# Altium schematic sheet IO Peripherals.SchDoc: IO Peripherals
size A4; DocumentNumber: 6; Revision: D.1(PCB.SCH); SheetNumber: 5; SheetTotal: 5
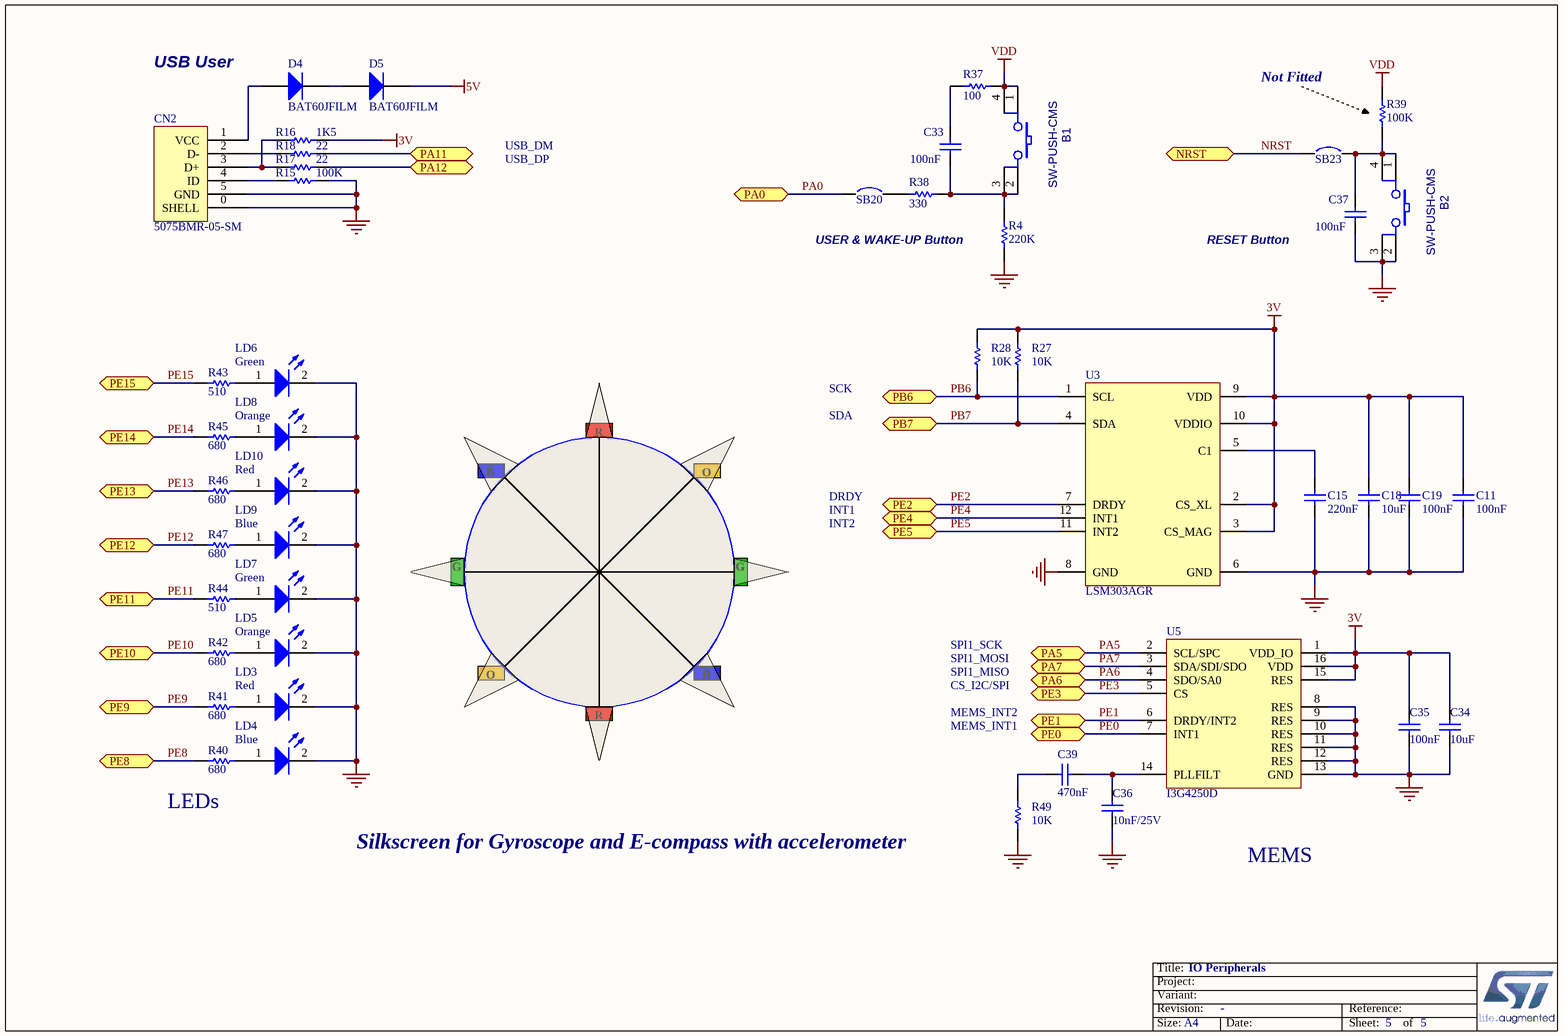
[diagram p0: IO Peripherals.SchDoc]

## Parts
B1  SW-PUSH-CMS  [BP1CMS]
B2  SW-PUSH-CMS  [BP1CMS]
C11  100nF  [0603C]
C15  220nF  [0603C]
C18  10uF  [0603C]
C19  100nF  [0603C]
C33  100nF  [0603C]
C34  10uF  [0603C]
C35  100nF  [0603C]
C36  10nF/25V  [0603C]
C37  100nF  [0603C]
C39  value 470nF  [C0603]  (hidden comment: Capacitor)
CN2  5075BMR-05-SM  [USB-MINI-B-SMD]
D4  BAT60JFILM  [SOD323/A]
D5  BAT60JFILM  [SOD323/A]
LD3  Red  [0603D]
LD4  Blue  [0603D]
LD5  Orange  [0603D]
LD6  Green  [0603D]
LD7  Green  [0603D]
LD8  Orange  [0603D]
LD9  Blue  [0603D]
LD10  Red  [0603D]
R4  220K  [0603R]
R15  100K  [0402R]
R16  1K5  [0402R]
R17  22  [0402R]
R18  22  [0402R]
R27  10K  [0402R]
R28  10K  [0402R]
R37  100  [0402R]
R38  330  [0402R]
R39  100K  [0402R]
R40  680  [0603R]
R41  680  [0603R]
R42  680  [0603R]
R43  510  [0603R]
R44  510  [0603R]
R45  680  [0603R]
R46  680  [0603R]
R47  680  [0603R]
R49  10K  [0402R]
SB20  Circuit Breaker  [JP2_SMD]  (value not drawn)
SB23  Circuit Breaker  [JP2_SMD]  (value not drawn)
U3  LSM303AGR  [ICC_LGA12_2X2_P050]
U5  I3G4250D  [ICC_LGA16_4X4_P065_H1P1]

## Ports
NRST, PA0, PA5, PA6, PA7, PA11, PA12, PB6, PB7, PE0, PE1, PE2, PE3, PE4, PE5, PE8, PE9, PE10, PE11, PE12, PE13, PE14, PE15

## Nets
3V: C11.1 C18.2 C19.2 C34.2 C35.2 R16.2 R27.1 R28.1 U3.2(CS_XL) U3.3(CS_MAG) U3.9(VDD) U3.10(VDDIO) U5.1(VDD_IO) U5.15(RES) U5.16(VDD)
5V: D5.2(K)
GND: B2.2 B2.3 C11.2 C15.1 C18.1 C19.1 C34.1 C35.1 C36.1 C37.1 CN2.0(SHELL) CN2.5(GND) LD3.2(K) LD4.2(K) LD5.2(K) LD6.2(K) LD7.2(K) LD8.2(K) LD9.2(K) LD10.2(K) R4.1 R15.2 R49.2 U3.6(GND) U3.8(GND) U5.8(RES) U5.9(RES) U5.10(RES) U5.11(RES) U5.12(RES) U5.13(GND)
VDD: B1.1 B1.4 R37.2 R39.2
NRST: SB23.1 ; port NRST
PA0: SB20.1 ; port PA0
PA5: U5.2(SCL/SPC) ; port PA5
PA6: U5.4(SDO/SA0) ; port PA6
PA7: U5.3(SDA/SDI/SDO) ; port PA7
PA11: R18.2 ; port PA11
PA12: R17.2 ; port PA12
PB6: R28.2 U3.1(SCL) ; port PB6
PB7: R27.2 U3.4(SDA) ; port PB7
PE0: U5.7(INT1) ; port PE0
PE1: U5.6(DRDY/INT2) ; port PE1
PE2: U3.7(DRDY) ; port PE2
PE3: U5.5(CS) ; port PE3
PE4: U3.12(INT1) ; port PE4
PE5: U3.11(INT2) ; port PE5
PE8: R40.2 ; port PE8
PE9: R41.2 ; port PE9
PE10: R42.2 ; port PE10
PE11: R44.2 ; port PE11
PE12: R47.2 ; port PE12
PE13: R46.2 ; port PE13
PE14: R45.2 ; port PE14
PE15: R43.2 ; port PE15
NetB1_2: B1.2 B1.3 C33.1 R4.2 R38.2
NetB2_1: B2.1 B2.4 C37.2 R39.1 SB23.2
NetC15_2: C15.2 U3.5(C1)
NetC33_2: C33.2 R37.1
NetC36_2: C36.2 C39.1 U5.14(PLLFILT)
NetC39_2: C39.2 R49.1
NetCN2_1: CN2.1(VCC) D4.1(A)
NetCN2_2: CN2.2(D-) R18.1
NetCN2_3: CN2.3(D+) R16.1 R17.1
NetCN2_4: CN2.4(ID) R15.1
NetD4_2: D4.2(K) D5.1(A)
NetLD3_1: LD3.1(A) R41.1
NetLD4_1: LD4.1(A) R40.1
NetLD5_1: LD5.1(A) R42.1
NetLD6_1: LD6.1(A) R43.1
NetLD7_1: LD7.1(A) R44.1
NetLD8_1: LD8.1(A) R45.1
NetLD9_1: LD9.1(A) R47.1
NetLD10_1: LD10.1(A) R46.1
NetR38_1: R38.1 SB20.2

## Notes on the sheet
- USB User
- Not Fitted
- USB_DM
- USB_DP
- USER & WAKE-UP Button
- RESET Button
- N
- R
- SCK
- SDA
- B
- O
- INT1
- DRDY
- W
- G
- E
- INT2
- SPI1_SCK
- SPI1_MOSI
- MEMS_INT2
- SPI1_MISO
- CS_I2C/SPI
- S
- MEMS_INT1
- (near R40) LEDs
- (near R49) Silkscreen for Gyroscope and E-compass with accelerometer
- MEMS

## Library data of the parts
B1 B2 = SW-PUSH-CMS: Non-Open Push-Button 0.1A 24V; Manuf_1: FARNELL; Manuf_Part_1: 535-930; Ref St: 9180120; cap_dec: ---
C11 C19 C33 C35 C37 = CAP: Capacitor
C15 C18 C34 C36 = CAP: Capacitor; Value: 100nF
C39 = MCD-01006: Capacitor, MLCC, 470nF, 16V, X7R, 10%, 0603, T=0.8mm; Manufacturer_Part_Number: CC0603KRX7R7BB474; Manufacturer: YAGEO; BMS_Part_Number: 9142003; Provided_By: SUBCO
CN2 = USB-MINI-typeB connector
D4 D5 = BAT60JFILM: Manuf_1: STM; Code - JEDEC: DO-214-AB; Provided: ST
LD3-LD10 = LED2: Typical RED, GREEN, YELLOW, AMBER GaAs LED
R4 = res1: Resistor; Value: 10K
R15 R16 R27 R28 R38 R49 = res1: Resistor
R17 R18 = res1: Resistor; Value: 1K5
R37 = res1: Resistor; Value: 330
R39 = res1: Resistor; Fitted: NO
R40-R47 = Res1: Resistor; Value: 1K
SB20 SB23 = Circuit Breaker: Solder: YES
U3 = MCD-00709: 3D accelerometer and 3D magnetometer; Part_Type: IC; Manufacturer: STMICROELECTRONICS; BMS_Part_Number: 9177057; ECCN_US: EAR99; ECCN_EU: NEC; Provided_By: SUBCO with ST control
U5 = MCD-01963: MEMS motion sensor: 3-axis digital output gyroscope LG4-16 4x4mm; Part_Type: IC; Manufacturer: STMICROELECTRONICS; ECCN_US: EAR99; ECCN_EU: NEC; Provided_By: SUBCO with ST control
